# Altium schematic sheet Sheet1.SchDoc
size A4
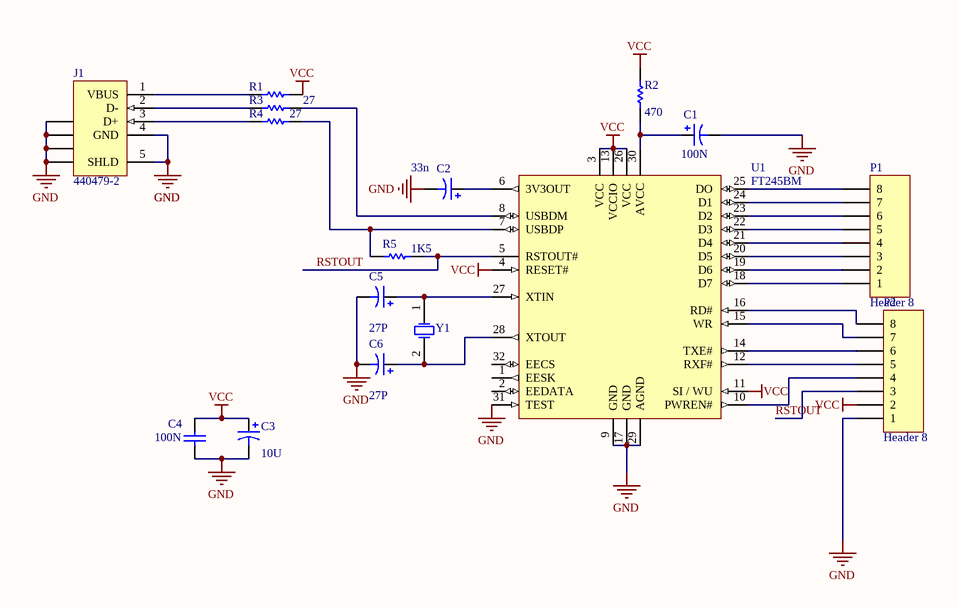
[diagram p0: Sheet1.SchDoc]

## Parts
C1  value 100N  [AXIAL-0.3]
C2  value 33n  [C0805]
C3  value 10U  [C0805]
C4  value 100N  [C1206]
C5  value 27P  [C0805]
C6  value 27P  [C0805]
J1  440479-2  [787780]
P1  Header 8  [HDR1X8]
P2  Header 8  [HDR1X8]
R1  (no value)  [AXIAL-0.3]
R2  value 470  [AXIAL-0.3]
R3  value 27  [2012[0805]]
R4  value 27  [2012[0805]]
R5  value 1K5  [2012[0805]]
U1  FT245BM  [LQFP-32_N]
Y1  (no value)  [HC-49U]

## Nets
GND: C1.2 C2.2 C3.2 C4.2 C5.2 C6.2 J1.4(GND) J1.5(SHLD) J1.6(SHLD) J1.7(SHLD) J1.8(SHLD) J1.9(SHLD) P2.1 U1.9(GND) U1.17(GND) U1.29(AGND) U1.31(TEST)
VCC: C3.1 C4.1 P2.2 R1.2 R2.1 U1.3(VCC) U1.4(RESET#) U1.11(SI_/_WU) U1.13(VCCIO) U1.26(VCC)
RSTOUT: P2.3 R5.2 U1.5(RSTOUT#)
NetC1_1: C1.1 R2.2 U1.30(AVCC)
NetC2_1: C2.1 U1.6(3V3OUT)
NetC5_1: C5.1 U1.27(XTIN) Y1.1(OSC1)
NetC6_1: C6.1 U1.28(XTOUT) Y1.2(OSC2)
NetJ1_1: J1.1(VBUS) R1.1
NetJ1_2: J1.2(D-) R3.1
NetJ1_3: J1.3(D+) R4.1
NetP1_1: P1.1 U1.18(D7)
NetP1_2: P1.2 U1.19(D6)
NetP1_3: P1.3 U1.20(D5)
NetP1_4: P1.4 U1.21(D4)
NetP1_5: P1.5 U1.22(D3)
NetP1_6: P1.6 U1.23(D2)
NetP1_7: P1.7 U1.24(D1)
NetP1_8: P1.8 U1.25(DO)
NetP2_4: P2.4 U1.10(PWREN#)
NetP2_5: P2.5 U1.12(RXF#)
NetP2_6: P2.6 U1.14(TXE#)
NetP2_7: P2.7 U1.15(WR)
NetP2_8: P2.8 U1.16(RD#)
NetR3_2: R3.2 U1.8(USBDM)
NetR4_2: R4.2 R5.1 U1.7(USBDP)

Not connected (* = marked no-connect by the designer): U1 1(EESK) 2(EEDATA) 32(EECS)

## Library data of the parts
C1-C3 C5 C6 = Cap Pol3: Polarized Capacitor (Surface Mount)
C4 = Cap Semi: Capacitor (Semiconductor SIM Model)
J1 = 440479-2: USB 2.0, Right Angle, SMT, AB Type, Receptacle, 5 Position, Black; ContactMaterial: Phosphor Bronze; ContactPlating: Gold (30) over Nickel; PCB_Layout: Complies with manufacturer's recommendation.; DrillSize: Corresponds to nominal value.; PanelGround: Without
P1 P2 = Header 8: Header, 8-Pin
R1 = Res1: Resistor
R2-R5 = Res Semi: Semiconductor Resistor
U1 = FT245BM: USB/Parallel FIFO Bi-Directional Data Transfer Chip, LQFP-32
Y1 = ECS-18-13-1: Crystal Oscillator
